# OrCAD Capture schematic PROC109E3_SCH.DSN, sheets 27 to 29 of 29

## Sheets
27 27. BOARD POWER 01: size C; title: BOARD POWER_01
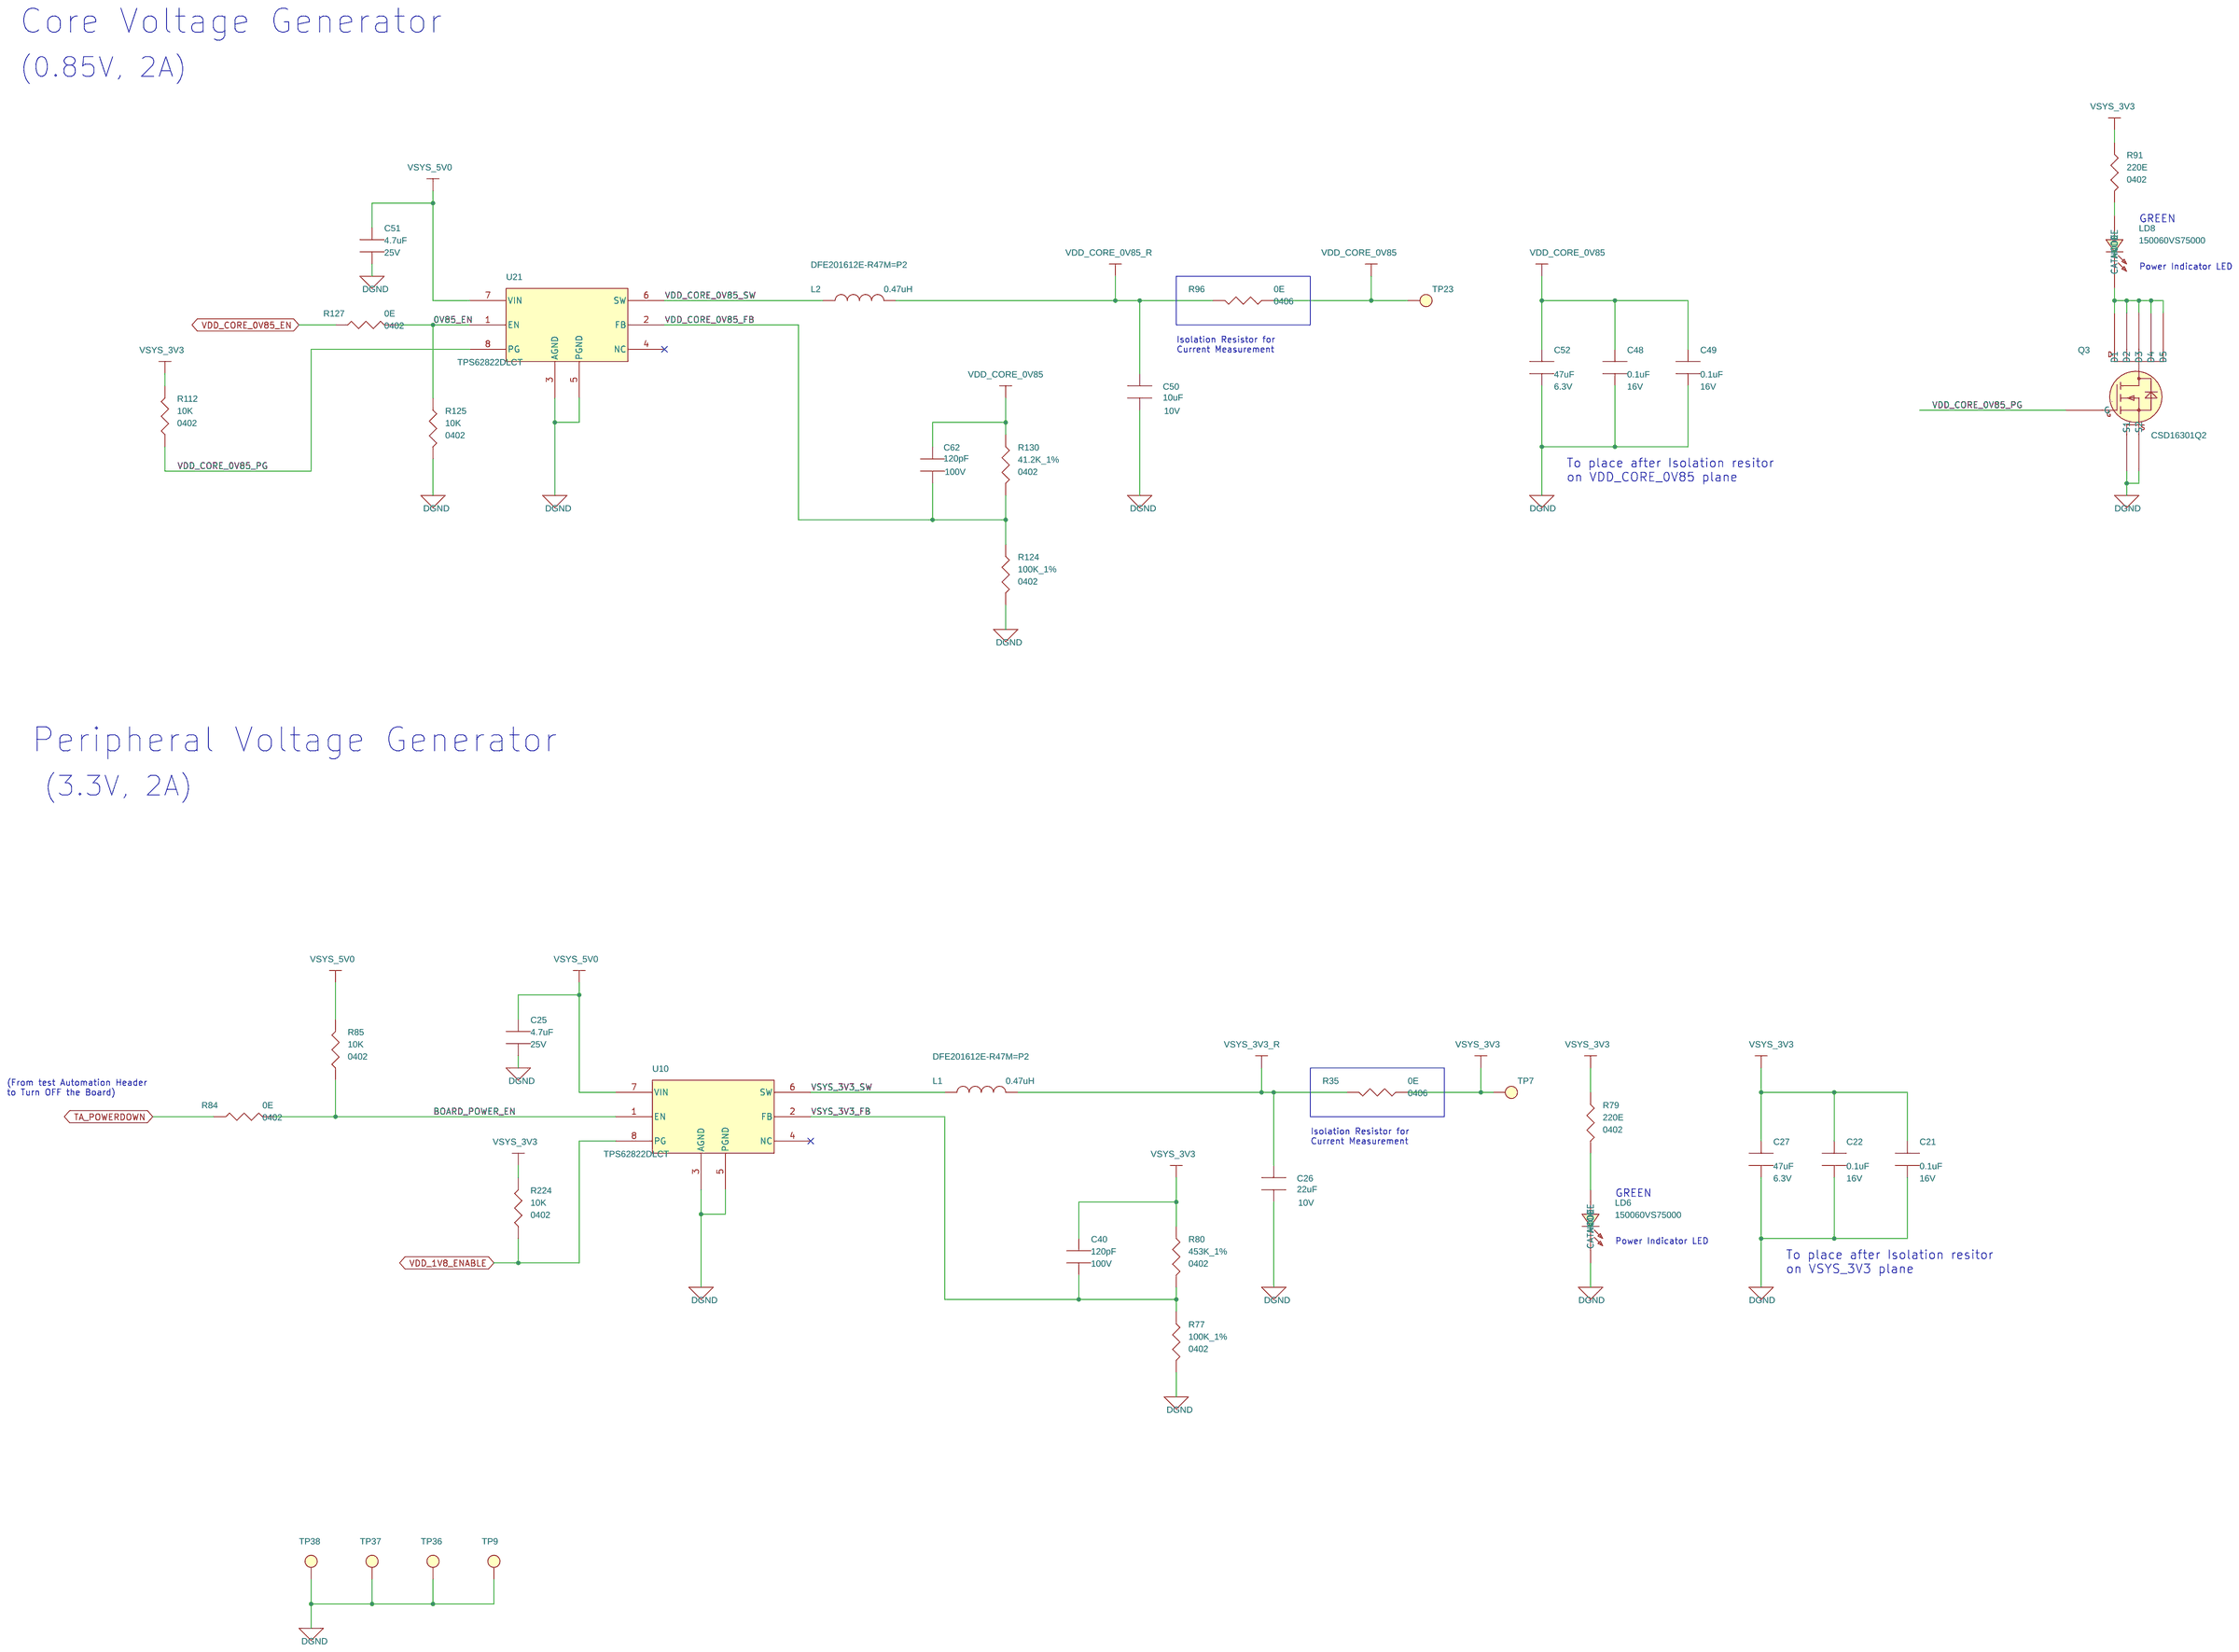
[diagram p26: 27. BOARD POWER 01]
28 28. BOARD POWER 02: size C; title: BOARD POWER_02
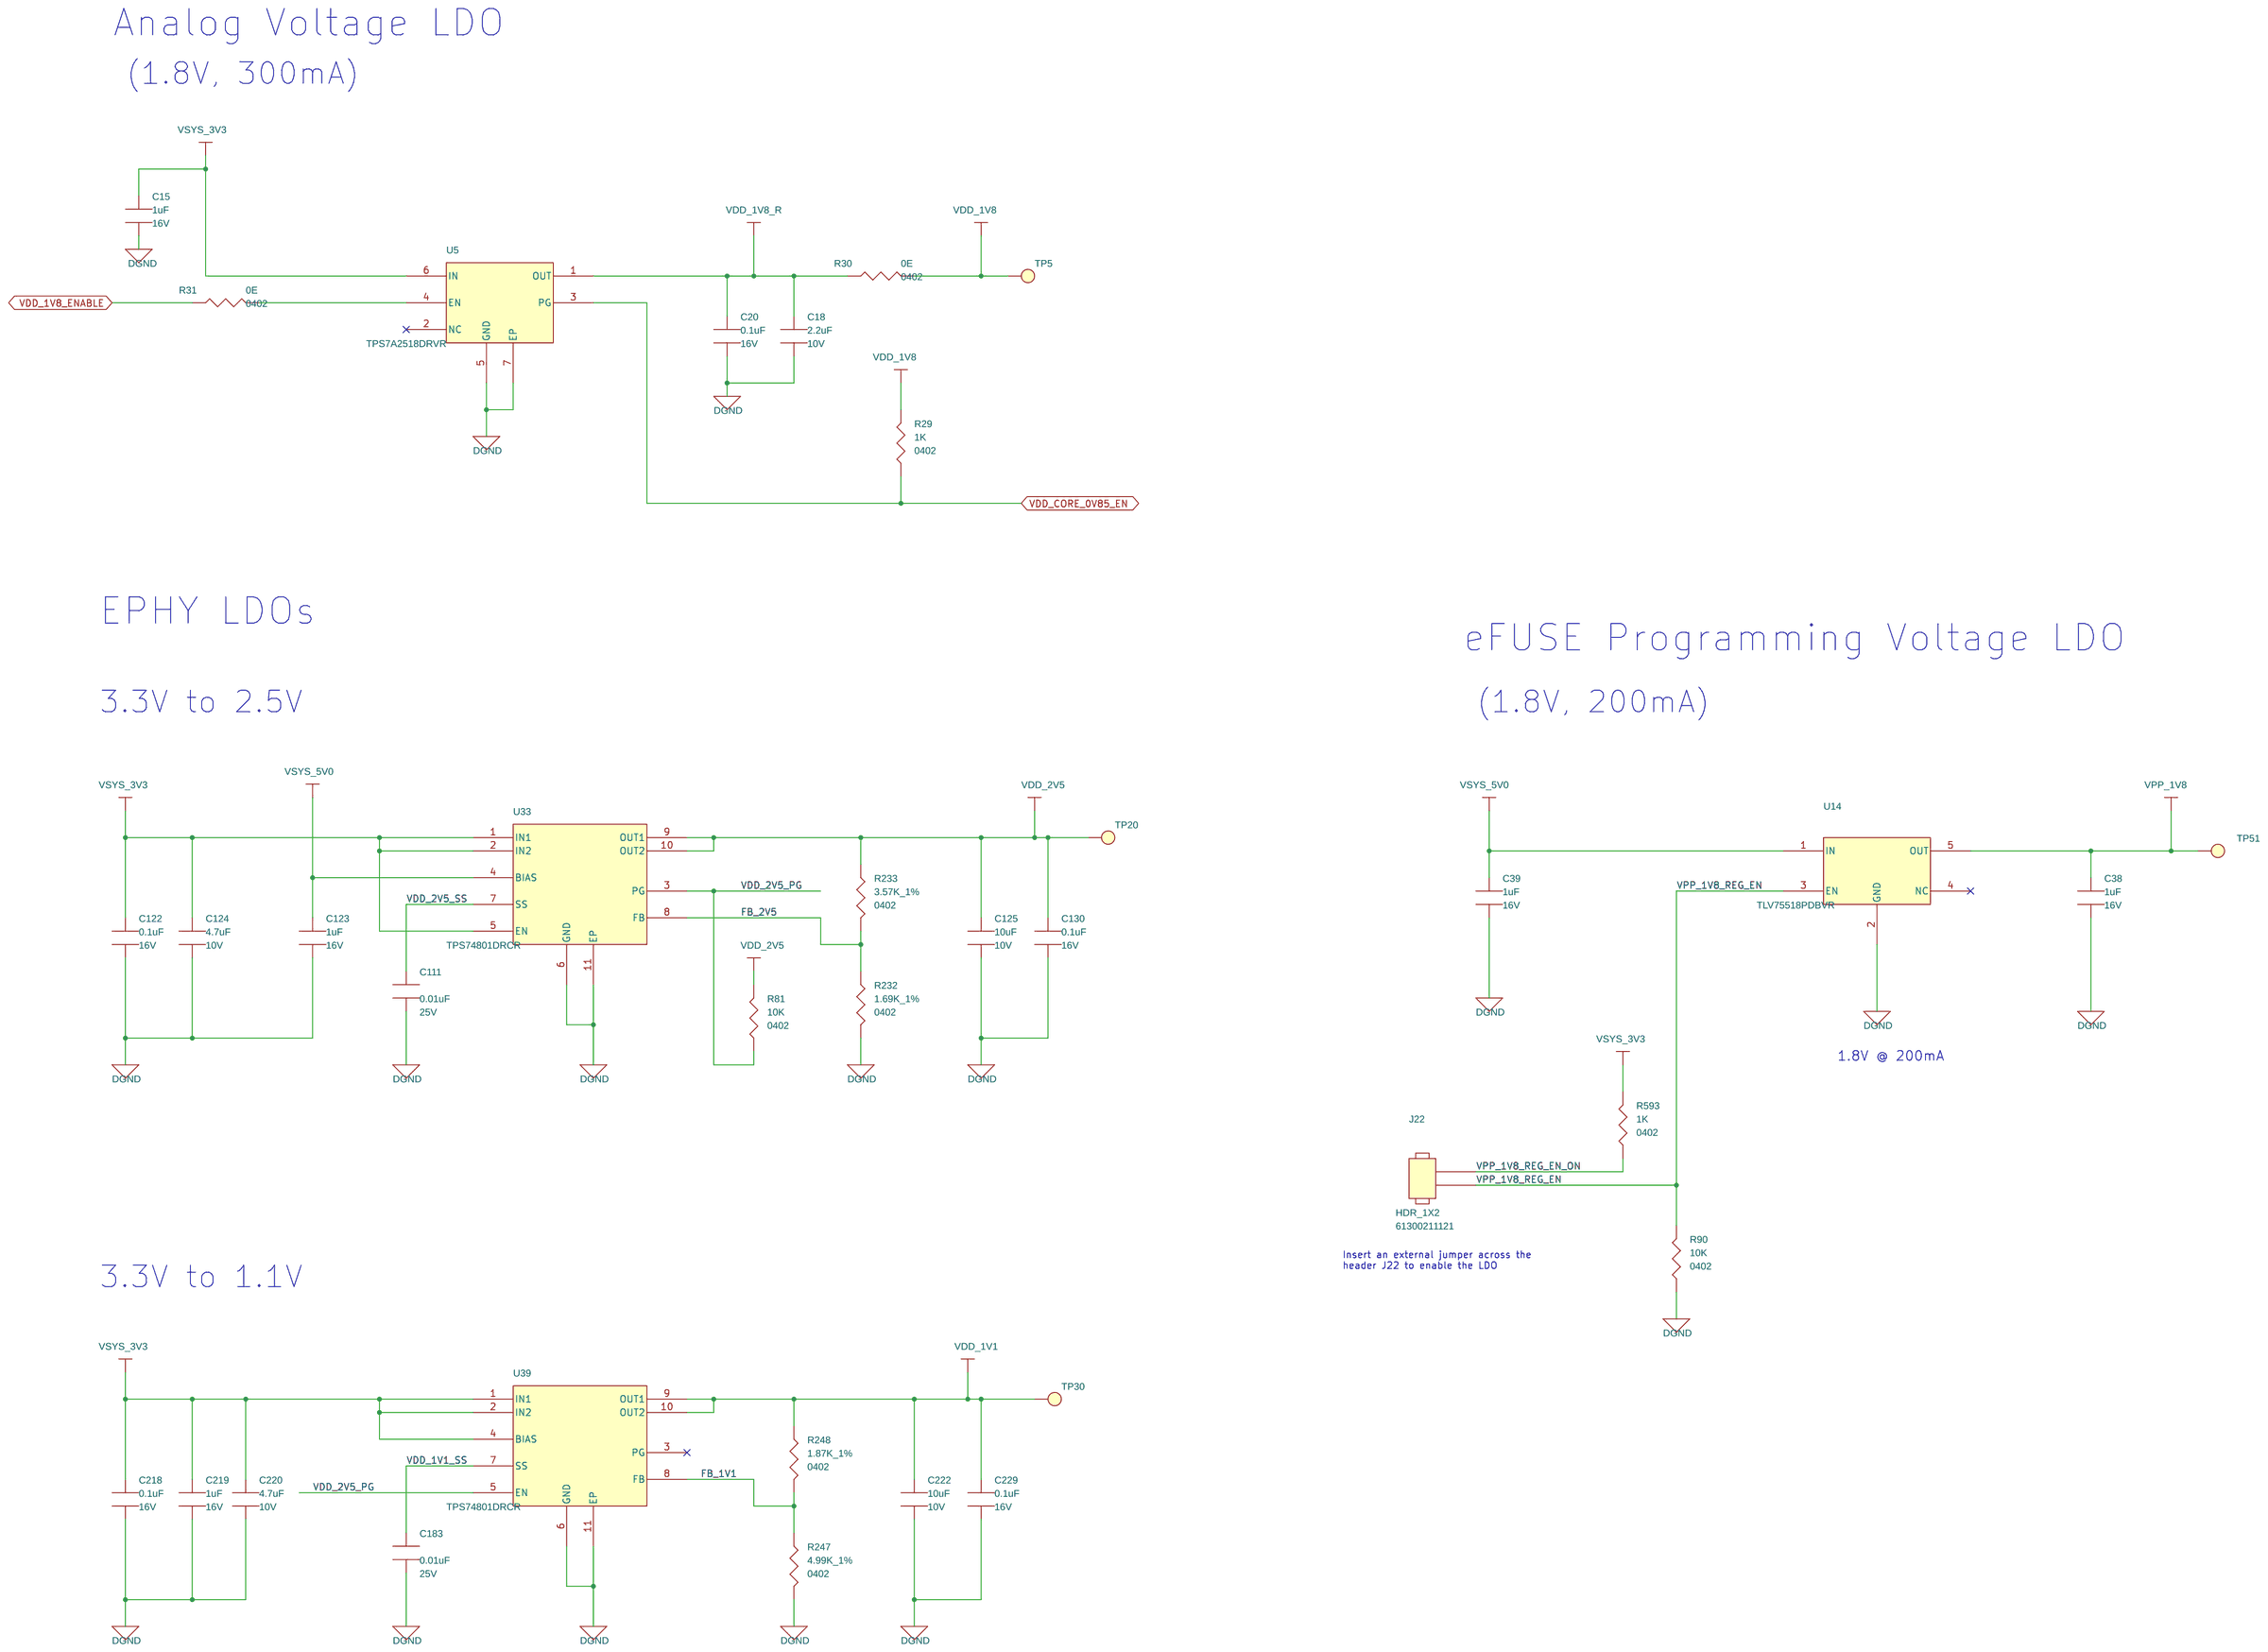
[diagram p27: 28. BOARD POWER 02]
29 29. HARDWARE_SCHEMATICS: title: HARDWARE SCHEMATICS
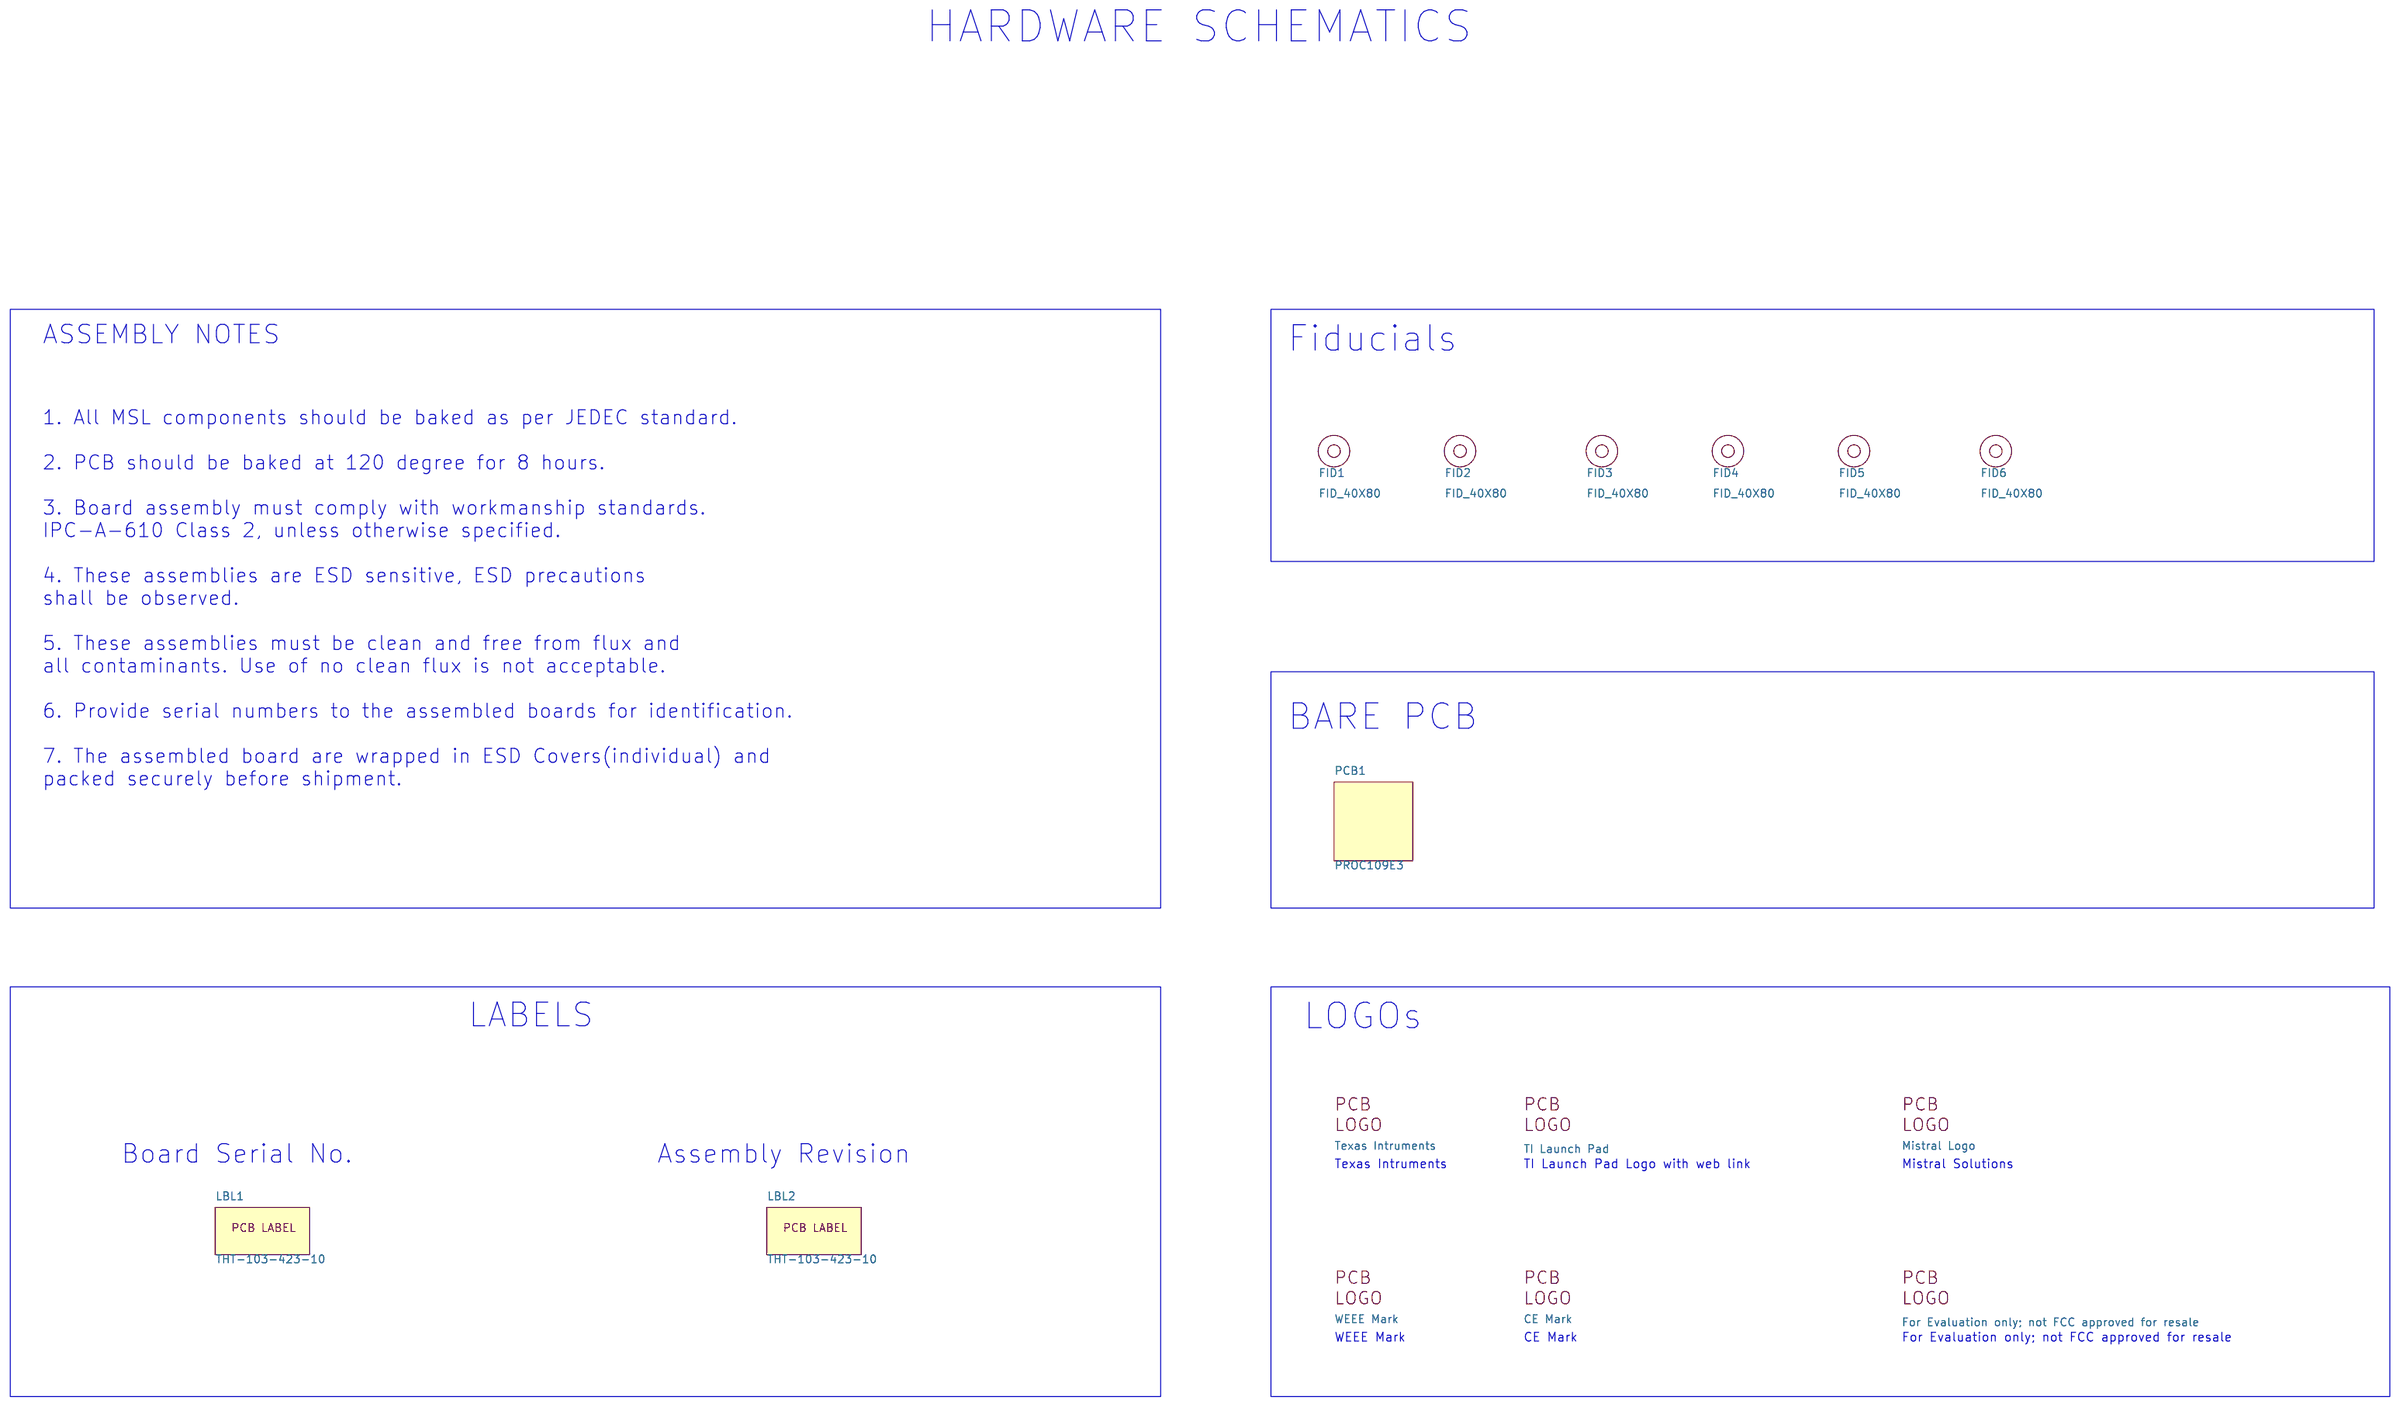
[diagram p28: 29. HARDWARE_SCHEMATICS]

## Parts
sheet 27. BOARD POWER 01
C21  0.1uF  [CAP0201_0-5]
C22  0.1uF  [CAP0201_0-5]
C25  4.7uF  [CAP1206_2]
C26  22uF  [CAP0603_1]
C27  47uF  [CAP0603_1]
C40  120pF  [CAP0402_0-75]
C48  0.1uF  [CAP0201_0-5]
C49  0.1uF  [CAP0201_0-5]
C50  10uF  [CAP0402_0-75]
C51  4.7uF  [CAP1206_2]
C52  47uF  [CAP0603_1]
C62  120pF  [CAP0402_0-75]
L1  0.47uH  [IND0806_1-2]
L2  0.47uH  [IND0806_1-2]
LD6  150060VS75000  [LED_150060SS75000_70X40_SMD_0-8]
LD8  150060VS75000  [LED_150060SS75000_70X40_SMD_0-8]
Q3  CSD16301Q2  [WSON6_CSD13202Q2_80X80_0-8]
R35  0E  [RES0406_0-5]
R77  100K_1%  [RES0402_0-5]
R79  220E  [RES0402_0-5]
R80  453K_1%  [RES0402_0-5]
R84  0E  [RES0402_0-5]
R85  10K  [RES0402_0-5]
R91  220E  [RES0402_0-5]
R96  0E  [RES0406_0-5]
R112  10K  [RES0402_0-5]
R124  100K_1%  [RES0402_0-5]
R125  10K  [RES0402_0-5]
R127  0E  [RES0402_0-5]
R130  41.2K_1%  [RES0402_0-5]
R224  10K  [RES0402_0-5]
TP7  TP40_SMD  [TP40_SMD]
TP9  THRU HOLE  [TP_40X65]
TP23  TP40_SMD  [TP40_SMD]
TP36  THRU HOLE  [TP_40X65]
TP37  THRU HOLE  [TP_40X65]
TP38  THRU HOLE  [TP_40X65]
U10  TPS62822DLCT  [VSONHR8_TPS62823_60X80_1]
U21  TPS62822DLCT  [VSONHR8_TPS62823_60X80_1]
sheet 28. BOARD POWER 02
C15  1uF  [CAP0201_0-5]
C18  2.2uF  [CAP0402_0-75]
C20  0.1uF  [CAP0201_0-5]
C38  1uF  [CAP0201_0-5]
C39  1uF  [CAP0201_0-5]
C111  0.01uF  [CAP0201_0-5]
C122  0.1uF  [CAP0201_0-5]
C123  1uF  [CAP0201_0-5]
C124  4.7uF  [CAP0402_0-75]
C125  10uF  [CAP0402_0-75]
C130  0.1uF  [CAP0201_0-5]
C183  0.01uF  [CAP0201_0-5]
C218  0.1uF  [CAP0201_0-5]
C219  1uF  [CAP0201_0-5]
C220  4.7uF  [CAP0402_0-75]
C222  10uF  [CAP0402_0-75]
C229  0.1uF  [CAP0201_0-5]
J22  HDR_1X2  [HDR_1X2_61300211121_S_T_8-6]
R29  1K  [RES0402_0-5]
R30  0E  [RES0402_0-5]
R31  0E  [RES0402_0-5]
R81  10K  [RES0402_0-5]
R90  10K  [RES0402_0-5]
R232  1.69K_1%  [RES0402_0-5]
R233  3.57K_1%  [RES0402_0-5]
R247  4.99K_1%  [RES0402_0-5]
R248  1.87K_1%  [RES0402_0-5]
R593  1K  [RES0402_0-5]
TP5  TP40_SMD  [TP40_SMD]
TP20  TP40_SMD  [TP40_SMD]
TP30  TP40_SMD  [TP40_SMD]
TP51  TP20_SMD  [TP20_SMD]
U5  TPS7A2518DRVR  [SON6_25-59_85X85_0-8]
U14  TLV75518PDBVR  [SOT23-5_1-5]
U33  TPS74801DRCR  [VSON10_TPS74801-Q1_120X120_1]
U39  TPS74801DRCR  [VSON10_TPS74801-Q1_120X120_1]
sheet 29. HARDWARE_SCHEMATICS
FID1  FID_40X80  [FID_40X80]
FID2  FID_40X80  [FID_40X80]
FID3  FID_40X80  [FID_40X80]
FID4  FID_40X80  [FID_40X80]
FID5  FID_40X80  [FID_40X80]
FID6  FID_40X80  [FID_40X80]
LBL1  THT-103-423-10  [NA]
LBL2  THT-103-423-10  [NA]
LOGO1  Texas Intruments  [TI_Stacked_Overlay_Small]
LOGO2  TI Launch Pad  [FCC_disclaimer]
LOGO3  Mistral Logo  [TI_Stacked_Overlay_Small]
LOGO4  WEEE Mark  [TI_Stacked_Overlay_Small]
LOGO5  CE Mark  [TI_Stacked_Overlay_Small]
LOGO6  For Evaluation only; not FCC approved for resale  [FCC_disclaimer]
PCB1  PROC109E3

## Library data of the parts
C20-C22 C48 C49 C122 C130 C218 C229 = CAP: CAP CERAMIC 0.1uF 16V 10% X5R 0201; Chkd/date: MANIRAJA/230118; Crtd /date: MANIRAJA/230118; Custom_Duty: 15%; Customs_HS_Code: 85322990; Distributor_name: DIGIKEY; Distributor_part_number: 490-14305-1-ND; Footprint Path: Y:\MIS_DATABASE\Library\ALTIUM_TOOL\PCB_FOOTPRINTS\Altium_Footprint_Lib.PcbLib; Height: 0.33MM; Library Path: Y:\MIS_DATABASE\Library\ALTIUM_TOOL\SCHEMATICS_PARTS\MS_DISCRETE_Library.schlib; Mfr_name: MURATA; Mfr_part_number: GRM033R61C104KE14D; Mistral Part No: 120009030072-R; Package: 0201; Part_type: CAPACITORS\CERAMIC; Project: TI_MAXIE_CPB; RoHS: RoHS; Temperature: -55°C+85°C; Tolerance: 10%; Voltage: 16V; Wattage: NA; Weight: 0.33mg; Datasheet: Y:\MIS_DATABASE\DATASHEETS\CAPACITORS\GRM033R61C104KE14.PDF
C25 C51 = CAP: CAP CERAMIC 4.7uF 25V 20% X5R 1206; Chkd/date: MANIRAJA/280121; Crtd /date: ALVY/280121; Custom_Duty: 15%; Customs_HS_Code: 85322990; Distributor_name: DIGIKEY; Distributor_part_number: 732-7644-1-ND; Footprint Path: Y:\MIS_DATABASE\Library\ALTIUM_TOOL\PCB_FOOTPRINTS\Altium_Footprint_Lib.PcbLib; Height: 1.90MM; Library Path: Y:\MIS_DATABASE\Library\ALTIUM_TOOL\SCHEMATICS_PARTS\MS_DISCRETE_Library.schlib; Mfr_name: WURTH ELECTRONICS; Mfr_part_number: 885012108020; Mistral Part No: 120021010031-R; Package: 1206; Part_type: CAPACITORS\CERAMIC; Project: TI_AM243x LP EVM; RoHS: RoHS; Temperature: -55°C+85°C; Tolerance: 20%; Voltage: 25V; Wattage: NA; Weight: 16.2mg; Datasheet: Y:\MIS_DATABASE\DATASHEETS\CAPACITORS\885012108020.PDF
C26 = CAP: CAP CERAMIC 22uF 10V 20% X5R 0603; Chkd/date: MANIRAJA/230118; Crtd /date: MANIRAJA/230118; Custom_Duty: 15%; Customs_HS_Code: 85322990; Distributor_name: DIGIKEY; Distributor_part_number: 490-10476-1-ND; Footprint Path: Y:\MIS_DATABASE\Library\ALTIUM_TOOL\PCB_FOOTPRINTS\Altium_Footprint_Lib.PcbLib; Height: 1.00MM; Library Path: Y:\MIS_DATABASE\Library\ALTIUM_TOOL\SCHEMATICS_PARTS\MS_DISCRETE_Library.schlib; Mfr_name: MURATA; Mfr_part_number: GRM188R61A226ME15D; Mistral Part No: 120014100009-R; Package: 0603; Part_type: CAPACITORS\CERAMIC; Project: TI_MAXIE_CPB; RoHS: RoHS; Temperature: -55°C+85°C; Tolerance: 20%; Voltage: 10V; Wattage: NA; Weight: 6.3mg; Datasheet: Y:\MIS_DATABASE\DATASHEETS\CAPACITORS\GRM188R61A226ME15.PDF
C27 C52 = CAP: CAP CERAMIC 47uF 6.3V 20% X5R 0603; Chkd/date: VASANTHA/211116; Crtd /date: MANIRAJA/211116; Custom_Duty: 15%; Customs_HS_Code: 85322990; Distributor_name: DIGIKEY; Distributor_part_number: 490-13247-1-ND; Footprint Path: Y:\MIS_DATABASE\Library\ALTIUM_TOOL\PCB_FOOTPRINTS\Altium_Footprint_Lib.PcbLib; Height: 1.00MM; Library Path: Y:\MIS_DATABASE\Library\ALTIUM_TOOL\SCHEMATICS_PARTS\MS_DISCRETE_Library.schlib; Mfr_name: MURATA; Mfr_part_number: GRM188R60J476ME15D; Mistral Part No: 120016110001-R; Package: 0603; Part_type: CAPACITORS\CERAMIC; Project: DLRL_3U_ESM_VPX; RoHS: RoHS; Temperature: -55°C+85°C; Tolerance: 20%; Voltage: 6.3V; Wattage: NA; Weight: 6.3mg; Datasheet: Y:\MIS_DATABASE\DATASHEETS\CAPACITORS\MURATA-GXX-SER_NOV17.PDF
C40 C62 = CAP: CAP CERAMIC 120pF 100V 5% C0G(NP0) 0402; Alternate_mfr_part_number_A: GCM1555C1H121JA16D; Chkd/date: MANIRAJA/280121; Crtd /date: ALVY/280121; Custom_Duty: 15%; Customs_HS_Code: 85322990; Distributor_name: MOUSER; Distributor_part_number: 81-GRM1555C2A121JE1D; Footprint Path: Y:\MIS_DATABASE\Library\ALTIUM_TOOL\PCB_FOOTPRINTS\Altium_Footprint_Lib.PcbLib; Height: 0.55MM; Library Path: Y:\MIS_DATABASE\Library\ALTIUM_TOOL\SCHEMATICS_PARTS\MS_DISCRETE_Library.schlib; Mfr_name: MURATA; Mfr_part_number: GRM1555C2A121JE01D; Mistral Part No: 120021010032-R; Package: 0402; Part_type: CAPACITORS\CERAMIC; Project: TI_AM243x LP EVM; RoHS: RoHS; Temperature: -55°C+125°C; Tolerance: 5%; Voltage: 100V; Wattage: NA; Weight: 1.6mg; Datasheet: Y:\MIS_DATABASE\DATASHEETS\CAPACITORS\GRM1555C2A121JE01.PDF
C50 C125 C222 = CAP: CAP CERAMIC 10uF 10V 20% X5R 0402; Chkd/date: MANIRAJA/300520; Crtd /date: ALVY/260520; Custom_Duty: 15%; Customs_HS_Code: 85322990; Distributor_name: DIGIKEY; Distributor_part_number: 490-GRM155R61A106ME11DTR-ND; Footprint Path: Y:\MIS_DATABASE\Library\ALTIUM_TOOL\PCB_FOOTPRINTS\Altium_Footprint_Lib.PcbLib; Height: 0.55MM; Library Path: Y:\MIS_DATABASE\Library\ALTIUM_TOOL\SCHEMATICS_PARTS\MS_DISCRETE_Library.schlib; Mfr_name: MURATA; Mfr_part_number: GRM155R61A106ME11D; Mistral Part No: 120013110019-R; Package: 0402; Part_type: CAPACITORS\CERAMIC; Project: QCS610_NANOSOM; RoHS: RoHS; Temperature: -55°C+85°C; Tolerance: 20%; Voltage: 10V; Wattage: NA; Weight: 3.1mg; Datasheet: Y:\MIS_DATABASE\DATASHEETS\CAPACITORS\MURATA-GXX-SER_NOV17.PDF
L1 L2 = INDUCTOR: IND CHIP 0.47uH 4.5A 20% 0806; Chkd/date: MANIRAJA/121020; Crtd /date: ALVY/121020; Custom_Duty: 24%; Customs_HS_Code: 85437099; Distributor_name: DIGIKEY; Distributor_part_number: DFE201612E-R47M=P2-ND; Footprint Path: Y:\MIS_DATABASE\Library\ALTIUM_TOOL\PCB_FOOTPRINTS\Altium_Footprint_Lib.PcbLib; Height: 1.20MM; Library Path: Y:\MIS_DATABASE\Library\ALTIUM_TOOL\SCHEMATICS_PARTS\MS_DISCRETE_Library.schlib; Mfr_name: MURATA; Mfr_part_number: DFE201612E-R47M=P2; Mistral Part No: 130020100030-R; Package: 0806; Project: AM64X_SKEVM; RoHS: RoHS; Temperature: -40°C+125°C; Tolerance: 20%; Voltage: NA; Wattage: NA; Weight: 18.8mg; Datasheet: Y:\MIS_DATABASE\DATASHEETS\DISCRETES\INDUCTORS\DFE201612E.PDF
LD6 LD8 = DIODE_LED: DIODE LED BRIGHT GREEN SMD; Chkd/date: MANIRAJA/220720; Crtd /date: ALVY/210720; Custom_Duty: 24%; Customs_HS_Code: 85439000; Distributor_name: DIGIKEY; Distributor_part_number: 732-4980-1-ND; Footprint Path: Y:\MIS_DATABASE\Library\ALTIUM_TOOL\PCB_FOOTPRINTS\Altium_Footprint_Lib.PcbLib; Height: 0.80MM; Library Path: Y:\MIS_DATABASE\Library\ALTIUM_TOOL\SCHEMATICS_PARTS\MS_OPTO_Library.schlib; Mfr_name: WURTH ELECTRONICS; Mistral Part No: 130020070019-R; Package: SMD; Part_type: OPTO\LED; Project: AM64x-IO LINK BRD; RoHS: RoHS; Temperature: -40°C+85°C; Tolerance: NA; Voltage: NA; Wattage: NA; Weight: 25mg; Datasheet: Y:\MIS_DATABASE\DATASHEETS\DISCRETES\LEDS\150060VS75000.PDF
Q3 = MOSFET_CSD17313Q2: IC MOSFET N-CHANNEL NEXFET 25V WSON6; Chkd/date: ALVY/071220; Crtd /date: MANIRAJA/071220; Custom_Duty: 15%; Customs_HS_Code: 85423100; Distributor_name: DIGIKEY; Distributor_part_number: 296-25260-1-ND; Footprint Path: Y:\MIS_DATABASE\Library\ALTIUM_TOOL\PCB_FOOTPRINTS\Altium_Footprint_Lib.PcbLib; Height: 0.80MM; Library Path: Y:\MIS_DATABASE\Library\ALTIUM_TOOL\SCHEMATICS_PARTS\MS_MOSFET_Library.schlib; Mfr_name: TEXAS INSTRUMENTS; Mistral Part No: 142020120008-R; Package: WSON6; Part_type: ICS\POWER\MOSFET; Project: TI_AM243x LP EVM; RoHS: RoHS; Temperature: -55°C+150°C; Tolerance: NA; Voltage: NA; Wattage: NA; Weight: 8.7mg; Datasheet: Y:\MIS_DATABASE\DATASHEETS\ICS\POWER\CSD16301Q2.PDF
R35 R96 = RESISTOR: RES 0E 1/4W JUMPER 0406; Chkd/date: MANIRAJA/250620; Crtd /date: ALVY/240620; Custom_Duty: 15%; Customs_HS_Code: 85332119; Distributor_name: DIGIKEY; Distributor_part_number: 749-1060-1-ND; Footprint Path: Y:\MIS_DATABASE\Library\ALTIUM_TOOL\PCB_FOOTPRINTS\Altium_Footprint_Lib.PcbLib; Height: 0.45MM; Library Path: Y:\MIS_DATABASE\Library\ALTIUM_TOOL\SCHEMATICS_PARTS\MS_DISCRETE_Library.schlib; Mfr_name: VISHAY; Mfr_part_number: RCA04060000Z0EALS; Mistral Part No: 110020060042-R; Package: 0406; Part_type: RESISTORS\FIXED; Project: ISSI TDA4VM; RoHS: RoHS; Temperature: -55°C+155°C; Tolerance: NA; Voltage: NA; Wattage: NA; Weight: 2mg; Datasheet: Y:\MIS_DATABASE\DATASHEETS\RESISTORS\RCA-LS.PDF
R77 R124 = RESISTOR: RES 100K 1/16W 1% 0402; Chkd/date: MANIRAJA/110917; Crtd /date: MANIRAJA/110917; Custom_Duty: 15%; Customs_HS_Code: 85332119; Distributor_name: DIGIKEY; Distributor_part_number: 311-100KLRCT-ND; Footprint Path: Y:\MIS_DATABASE\Library\ALTIUM_TOOL\PCB_FOOTPRINTS\Altium_Footprint_Lib.PcbLib; Height: 0.40MM; Library Path: Y:\MIS_DATABASE\Library\ALTIUM_TOOL\SCHEMATICS_PARTS\MS_DISCRETE_Library.schlib; Mfr_name: YAGEO AMERICA; Mfr_part_number: RC0402FR-07100KL; Mistral Part No: 110014060043-R; Package: 0402; Part_type: RESISTORS\FIXED; Project: CRADE RF CARD; RoHS: RoHS; Temperature: -55°C+155°C; Tolerance: 1%; Voltage: NA; Wattage: 1/16W; Weight: 0.65mg; Datasheet: Y:\MIS_DATABASE\DATASHEETS\RESISTORS\RCXXXXL-SER_MAR18.PDF
R79 R91 = RESISTOR: RES 220E 1/16W 5% 0402; Chkd/date: ALVY/091220; Crtd /date: MANIRAJA/091220; Custom_Duty: 15%; Customs_HS_Code: 85332119; Distributor_name: DIGIKEY; Distributor_part_number: 311-220JRCT-ND; Footprint Path: Y:\MIS_DATABASE\Library\ALTIUM_TOOL\PCB_FOOTPRINTS\Altium_Footprint_Lib.PcbLib; Height: 0.40MM; Library Path: Y:\MIS_DATABASE\Library\ALTIUM_TOOL\SCHEMATICS_PARTS\MS_DISCRETE_Library.schlib; Mfr_name: YAGEO AMERICA; Mfr_part_number: RC0402JR-07220RL; Mistral Part No: 110020120013-R; Package: 0402; Part_type: RESISTORS\FIXED; Project: TI_AM243x LP EVM; RoHS: RoHS; Temperature: -55°C+155°C; Tolerance: 5%; Voltage: NA; Wattage: 1/16W; Weight: 0.65mg; Datasheet: Y:\MIS_DATABASE\DATASHEETS\RESISTORS\RCXXXXL-SER_MAR18.PDF
R80 = RESISTOR: RES 453K 1/16W 1% 0402; Chkd/date: MANIRAJA/150519; Crtd /date: MANIRAJA/150519; Custom_Duty: 15%; Customs_HS_Code: 85332119; Distributor_name: DIGIKEY; Distributor_part_number: YAG3164CT-ND; Footprint Path: Y:\MIS_DATABASE\Library\ALTIUM_TOOL\PCB_FOOTPRINTS\Altium_Footprint_Lib.PcbLib; Height: 0.40MM; Library Path: Y:\MIS_DATABASE\Library\ALTIUM_TOOL\SCHEMATICS_PARTS\MS_DISCRETE_Library.schlib; Mfr_name: YAGEO AMERICA; Mfr_part_number: RC0402FR-07453KL; Mistral Part No: 110019050018-R; Package: 0402; Part_type: RESISTORS\FIXED; Project: AM654x SOM_TEST_JIG; RoHS: RoHS; Temperature: -55°C+155°C; Tolerance: 1%; Voltage: NA; Wattage: 1/16W; Weight: 0.65mg; Datasheet: Y:\MIS_DATABASE\DATASHEETS\RESISTORS\RCXXXXL-SER_MAR18.PDF
R30 R31 R84 R127 = RESISTOR: RES 0E 1/16W 5% 0402; Chkd/date: VASANTHA/291216; Crtd /date: CHAITHANYA/300911; Custom_Duty: 15%; Customs_HS_Code: 85332119; Distributor_name: DIGIKEY; Distributor_part_number: 311-0.0JRCT-ND; Footprint Path: Y:\MIS_DATABASE\Library\ALTIUM_TOOL\PCB_FOOTPRINTS\Altium_Footprint_Lib.PcbLib; Height: 0.40MM; Library Path: Y:\MIS_DATABASE\Library\ALTIUM_TOOL\SCHEMATICS_PARTS\MS_DISCRETE_Library.schlib; Mfr_name: YAGEO AMERICA; Mfr_part_number: RC0402JR-070RL; Mistral Part No: 110011090036-R; Package: 0402; Part_type: RESISTORS\FIXED; Project: VP-4000-PROCESSOR; RoHS: RoHS; Temperature: -55°C+155°C; Tolerance: 5%; Voltage: NA; Wattage: 1/16W; Weight: 0.65mg; Datasheet: Y:\MIS_DATABASE\DATASHEETS\RESISTORS\RCXXXXL-SER_MAR18.PDF
R81 R85 R90 R112 R125 R224 = RESISTOR: RES 10K 1/16W 5% 0402; Chkd/date: VASANTHA/061216; Crtd /date: MAZHAR/230805; Custom_Duty: 15%; Customs_HS_Code: 85332119; Distributor_name: DIGIKEY; Distributor_part_number: 311-10KJRCT-ND; Footprint Path: Y:\MIS_DATABASE\Library\ALTIUM_TOOL\PCB_FOOTPRINTS\Altium_Footprint_Lib.PcbLib; Height: 0.40MM; Library Path: Y:\MIS_DATABASE\Library\ALTIUM_TOOL\SCHEMATICS_PARTS\MS_DISCRETE_Library.schlib; Mfr_name: YAGEO AMERICA; Mfr_part_number: RC0402JR-0710KL; Mistral Part No: 110011060021-R; Package: 0402; Part_type: RESISTORS\FIXED; Project: HSE; RoHS: RoHS; Temperature: -55°C+155°C; Tolerance: 5%; Voltage: NA; Wattage: 1/16W; Weight: 0.65mg; Datasheet: Y:\MIS_DATABASE\DATASHEETS\RESISTORS\RCXXXXL-SER_MAR18.PDF
R130 = RESISTOR: RES 41.2K 1/16W 1% 0402; Chkd/date: ALVY/091220; Crtd /date: MANIRAJA/091220; Custom_Duty: 15%; Customs_HS_Code: 85332119; Distributor_name: DIGIKEY; Distributor_part_number: YAG3155CT-ND; Footprint Path: Y:\MIS_DATABASE\Library\ALTIUM_TOOL\PCB_FOOTPRINTS\Altium_Footprint_Lib.PcbLib; Height: 0.40MM; Library Path: Y:\MIS_DATABASE\Library\ALTIUM_TOOL\SCHEMATICS_PARTS\MS_DISCRETE_Library.schlib; Mfr_name: YAGEO AMERICA; Mfr_part_number: RC0402FR-0741K2L; Mistral Part No: 110020050005-R; Package: 0402; Part_type: RESISTORS\FIXED; Project: TI_AM243x LP EVM; RoHS: RoHS; Temperature: -55°C+155°C; Tolerance: 1%; Voltage: NA; Wattage: 1/16W; Weight: 0.65mg; Datasheet: Y:\MIS_DATABASE\DATASHEETS\RESISTORS\RCXXXXL-SER_MAR18.PDF
TP5 TP7 TP20 TP23 TP30 = TESTPOINT: TESTPOINT CIR 40 SMD; Chkd/date: MAZHAR/190505; Crtd /date: MAZHAR/190505; Distributor_name: NA; Distributor_part_number: NA; Footprint Path: Y:\MIS_DATABASE\Library\ALTIUM_TOOL\PCB_FOOTPRINTS\Altium_Footprint_Lib.PcbLib; Height: NA; Library Path: Y:\MIS_DATABASE\Library\ALTIUM_TOOL\SCHEMATICS_PARTS\MS_DISCRETE_Library.schlib; MECHANICAL 3D STEP FILE: NA; Mfr_name: LOCAL; Mistral Part No: 130009030933; Package: SMD; Project: RAINIER-3; RoHS: NA; Temperature: NA; Tolerance: NA; Voltage: NA; Wattage: NA; Weight: NA; Datasheet: NA
TP9 TP36-TP38 = TESTPOINT: TESTPOINT 1.0MM DRILL PTH; Chkd/date: MAZHAR/271211; Crtd /date: SHREESHAIL/041005; Distributor_name: NA; Distributor_part_number: NA; Height: NA; Mfr_name: LOCAL; Mistral Part No: 130009030938; Package: THRU-HOLE; Project: HSE; Datasheet: NA
U10 U21 = TPS62823_VSONHR8: IC 2A ADJ STEP-DOWN CONVERTER WITH 1% ACCURACY VSON-HR8; Chkd/date: MANIRAJA/121120; Crtd /date: ALVY/111120; Custom_Duty: 15%; Customs_HS_Code: 85423100; Distributor_name: DIGIKEY; Distributor_part_number: 296-49512-1-ND; Footprint Path: Y:\MIS_DATABASE\Library\ALTIUM_TOOL\PCB_FOOTPRINTS\Altium_Footprint_Lib.PcbLib; Height: 1.00MM; Library Path: Y:\MIS_DATABASE\Library\ALTIUM_TOOL\SCHEMATICS_PARTS\MS_MISCPOWER_Library.schlib; Mfr_name: TEXAS INSTRUMENTS; Mistral Part No: 142020110014-R; Package: VSON-HR8; Part_type: ICS\POWER\DC-DC CONVERTER; Project: TI_AM243x LP EVM; RoHS: RoHS; Temperature: -40°C+125°C; Tolerance: NA; Voltage: NA; Wattage: NA; Weight: 6.2mg; Datasheet: Y:\MIS_DATABASE\DATASHEETS\ICS\POWER\TPS62821-2-3.PDF
C15 C38 C39 C123 C219 = CAP: CAP CERAMIC 1uF 16V 20% X5R 0201; Chkd/date: MANIRAJA/300520; Crtd /date: ALVY/260520; Custom_Duty: 15%; Customs_HS_Code: 85322990; Distributor_name: DIGIKEY; Distributor_part_number: 490-18654-1-ND; Footprint Path: Y:\MIS_DATABASE\Library\ALTIUM_TOOL\PCB_FOOTPRINTS\Altium_Footprint_Lib.PcbLib; Height: 0.39MM; Library Path: Y:\MIS_DATABASE\Library\ALTIUM_TOOL\SCHEMATICS_PARTS\MS_DISCRETE_Library.schlib; Mfr_name: MURATA; Mfr_part_number: GRM033R61C105ME15D; Mistral Part No: 120018090038-R; Package: 0201; Part_type: CAPACITORS\CERAMIC; Project: QCS610_NANOSOM; RoHS: RoHS; Temperature: -55°C+85°C; Tolerance: 20%; Voltage: 16V; Wattage: NA; Weight: 0.33mg; Datasheet: Y:\MIS_DATABASE\DATASHEETS\CAPACITORS\GRM033R61C105ME15.PDF
C18 = CAP: CAP CERAMIC 2.2uF 10V 20% X5R 0402; Chkd/date: MANIRAJA/170820; Crtd /date: ALVY/170820; Custom_Duty: 15%; Customs_HS_Code: 85322990; Distributor_name: DIGIKEY; Distributor_part_number: 732-7490-1-ND; Footprint Path: Y:\MIS_DATABASE\Library\ALTIUM_TOOL\PCB_FOOTPRINTS\Altium_Footprint_Lib.PcbLib; Height: 0.55MM; Library Path: Y:\MIS_DATABASE\Library\ALTIUM_TOOL\SCHEMATICS_PARTS\MS_DISCRETE_Library.schlib; Mfr_name: WURTH ELECTRONICS; Mfr_part_number: 885012105013; Mistral Part No: 120019040036-R; Package: 0402; Part_type: CAPACITORS\CERAMIC; Project: AM64x_EVM_BRD; RoHS: RoHS; Temperature: -55°C+85°C; Tolerance: 20%; Voltage: 10V; Wattage: NA; Weight: 0.65mg; Datasheet: Y:\MIS_DATABASE\DATASHEETS\CAPACITORS\885012105013.PDF
C111 C183 = CAP: CAP CERAMIC 0.01uF 25V 10% X7R 0201; Chkd/date: MANIRAJA/080519; Crtd /date: ALVY/080519; Custom_Duty: 15%; Customs_HS_Code: 85322990; Distributor_name: DIGIKEY; Distributor_part_number: 490-14454-1-ND; Footprint Path: Y:\MIS_DATABASE\Library\ALTIUM_TOOL\PCB_FOOTPRINTS\Altium_Footprint_Lib.PcbLib; Height: 0.33MM; Library Path: Y:\MIS_DATABASE\Library\ALTIUM_TOOL\SCHEMATICS_PARTS\MS_DISCRETE_Library.schlib; Mfr_name: MURATA; Mfr_part_number: GRM033R71E103KE14D; Mistral Part No: 120019050002-R; Package: 0201; Part_type: CAPACITORS\CERAMIC; Project: BRUKER_SD820_COMMONDO; RoHS: RoHS; Temperature: -55°C+125°C; Tolerance: 10%; Voltage: 25V; Wattage: NA; Weight: 0.33mg; Datasheet: Y:\MIS_DATABASE\DATASHEETS\CAPACITORS\GRM033R71E103KE14.PDF
C124 C220 = CAP: CAP CERAMIC 4.7uF 10V 20% X5R 0402; Chkd/date: MANIRAJA/110718; Crtd /date: ALVY/110718; Custom_Duty: 15%; Customs_HS_Code: 85322990; Distributor_name: DIGIKEY; Distributor_part_number: 490-14306-1-ND; Footprint Path: Y:\MIS_DATABASE\Library\ALTIUM_TOOL\PCB_FOOTPRINTS\Altium_Footprint_Lib.PcbLib; Height: 0.65MM; Library Path: Y:\MIS_DATABASE\Library\ALTIUM_TOOL\SCHEMATICS_PARTS\MS_DISCRETE_Library.schlib; Mfr_name: MURATA; Mfr_part_number: GRM155R61A475MEAAD; Mistral Part No: 120012060002-R; Package: 0402; Part_type: CAPACITORS\CERAMIC; Project: TI_J7SVB_PCIE_ADD-ON-CARD; RoHS: RoHS; Temperature: -55°C+85°C; Tolerance: 20%; Voltage: 10V; Wattage: NA; Weight: 14mg; Datasheet: Y:\MIS_DATABASE\DATASHEETS\CAPACITORS\GRM155R61A475MEAAD.PDF
J22 = HEADER_2X1: CON HDR 1X2 2.54MM PITCH ST TH; Chkd/date: MANIRAJA/031018; Crtd /date: ALVY/031018; Custom_Duty: 24%; Customs_HS_Code: 85369090; Distributor_name: DIGIKEY; Distributor_part_number: 732-5315-ND; Footprint Path: Y:\MIS_DATABASE\Library\ALTIUM_TOOL\PCB_FOOTPRINTS\Altium_Footprint_Lib.PcbLib; Height: 8.54MM; Library Path: Y:\MIS_DATABASE\Library\ALTIUM_TOOL\SCHEMATICS_PARTS\MS_CONNECTOR_Library.schlib; Mfr_name: WURTH ELECTRONICS; Mfr_part_number: 61300211121; Mistral Part No: 150018100003-R; Package: THRU-HOLE; Part_type: CONNECTOR\HEADERS; Project: ALPINE_EVM; RoHS: RoHS; Temperature: -40°C+105°C; Tolerance: NA; Voltage: NA; Wattage: NA; Weight: 120mg; Datasheet: Y:\MIS_DATABASE\DATASHEETS\CONNECTORS\6130XXX.PDF
R29 R593 = RESISTOR: RES 1K 1/16W 5% 0402; Chkd/date: VASANTHA/120516; Crtd /date: VASANTHA/120516; Custom_Duty: 15%; Customs_HS_Code: 85332119; Distributor_name: DIGIKEY; Distributor_part_number: 311-1.0KJRCT-ND; Footprint Path: Y:\MIS_DATABASE\Library\ALTIUM_TOOL\PCB_FOOTPRINTS\Altium_Footprint_Lib.PcbLib; Height: 0.40MM; Library Path: Y:\MIS_DATABASE\Library\ALTIUM_TOOL\SCHEMATICS_PARTS\MS_DISCRETE_Library.schlib; Mfr_name: YAGEO AMERICA; Mfr_part_number: RC0402JR-071KL; Mistral Part No: 110010070006-R; Package: 0402; Part_type: RESISTORS\FIXED; Project: TMDXCSK368; RoHS: RoHS; Temperature: -55°C+155°C; Tolerance: 5%; Voltage: NA; Wattage: 1/16W; Weight: 0.65mg; Datasheet: Y:\MIS_DATABASE\DATASHEETS\RESISTORS\RCXXXXL-SER_MAR18.PDF
R232 = RESISTOR: RES 1.69K 1/16W 1% 0402; Chkd/date: ALVY/091220; Crtd /date: MANIRAJA/091220; Custom_Duty: 15%; Customs_HS_Code: 85332119; Distributor_name: DIGIKEY; Distributor_part_number: YAG3044CT-ND; Footprint Path: Y:\MIS_DATABASE\Library\ALTIUM_TOOL\PCB_FOOTPRINTS\Altium_Footprint_Lib.PcbLib; Height: 0.40MM; Library Path: Y:\MIS_DATABASE\Library\ALTIUM_TOOL\SCHEMATICS_PARTS\MS_DISCRETE_Library.schlib; Mfr_name: YAGEO AMERICA; Mfr_part_number: RC0402FR-071K69L; Mistral Part No: 110018100013-R; Package: 0402; Part_type: RESISTORS\FIXED; Project: TI_AM243x LP EVM; RoHS: RoHS; Temperature: -55°C+155°C; Tolerance: 1%; Voltage: NA; Wattage: 1/16W; Weight: 0.65mg; Datasheet: Y:\MIS_DATABASE\DATASHEETS\RESISTORS\RCXXXXL-SER_MAR18.PDF
R233 = RESISTOR: RES 3.57K 1/16W 1% 0402; Chkd/date: ALVY/091220; Crtd /date: MANIRAJA/091220; Custom_Duty: 15%; Customs_HS_Code: 85332119; Distributor_name: DIGIKEY; Distributor_part_number: YAG3150CT-ND; Footprint Path: Y:\MIS_DATABASE\Library\ALTIUM_TOOL\PCB_FOOTPRINTS\Altium_Footprint_Lib.PcbLib; Height: 0.40MM; Library Path: Y:\MIS_DATABASE\Library\ALTIUM_TOOL\SCHEMATICS_PARTS\MS_DISCRETE_Library.schlib; Mfr_name: YAGEO AMERICA; Mfr_part_number: RC0402FR-073K57L; Mistral Part No: 110009070012-R; Package: 0402; Part_type: RESISTORS\FIXED; Project: TI_AM243x LP EVM; RoHS: RoHS; Temperature: -55°C+155°C; Tolerance: 1%; Voltage: NA; Wattage: 1/16W; Weight: 0.65mg; Datasheet: Y:\MIS_DATABASE\DATASHEETS\RESISTORS\RCXXXXL-SER_MAR18.PDF
R247 = RESISTOR: RES 4.99K 1/16W 1% 0402; Chkd/date: MANIRAJA/181120; Crtd /date: ALVY/171120; Custom_Duty: 15%; Customs_HS_Code: 85332119; Distributor_name: DIGIKEY; Distributor_part_number: 311-4.99KLRCT-ND; Footprint Path: Y:\MIS_DATABASE\Library\ALTIUM_TOOL\PCB_FOOTPRINTS\Altium_Footprint_Lib.PcbLib; Height: 0.40MM; Library Path: Y:\MIS_DATABASE\Library\ALTIUM_TOOL\SCHEMATICS_PARTS\MS_DISCRETE_Library.schlib; Mfr_name: YAGEO AMERICA; Mfr_part_number: RC0402FR-074K99L; Mistral Part No: 110014070062-R; Package: 0402; Part_type: RESISTORS\FIXED; Project: SAMSUNG_STREAM_RF; RoHS: RoHS; Temperature: -55°C+155°C; Tolerance: 1%; Voltage: NA; Wattage: 1/16W; Weight: 9mg; Datasheet: Y:\MIS_DATABASE\DATASHEETS\RESISTORS\RCXXXXL-SER_MAR18.PDF
R248 = RESISTOR: RES 1.87K 1/16W 1% 0402; Chkd/date: ALVY/091220; Crtd /date: MANIRAJA/091220; Custom_Duty: 15%; Customs_HS_Code: 85332119; Distributor_name: DIGIKEY; Distributor_part_number: YAG3048CT-ND; Footprint Path: Y:\MIS_DATABASE\Library\ALTIUM_TOOL\PCB_FOOTPRINTS\Altium_Footprint_Lib.PcbLib; Height: 0.40MM; Library Path: Y:\MIS_DATABASE\Library\ALTIUM_TOOL\SCHEMATICS_PARTS\MS_DISCRETE_Library.schlib; Mfr_name: YAGEO AMERICA; Mfr_part_number: RC0402FR-071K87L; Mistral Part No: 110020120012-R; Package: 0402; Part_type: RESISTORS\FIXED; Project: TI_AM243x LP EVM; RoHS: RoHS; Temperature: -55°C+155°C; Tolerance: 1%; Voltage: NA; Wattage: 1/16W; Weight: 0.65mg; Datasheet: Y:\MIS_DATABASE\DATASHEETS\RESISTORS\RCXXXXL-SER_MAR18.PDF
TP51 = TESTPOINT: TESTPOINT CIR 20 SMD; Chkd/date: SHREESHAIL/171006; Crtd /date: MAZHAR/171006; Custom_Duty: NA; Customs_HS_Code: NA; Distributor_name: NA; Distributor_part_number: NA; Footprint Path: Y:\MIS_DATABASE\Library\ALTIUM_TOOL\PCB_FOOTPRINTS\Altium_Footprint_Lib.PcbLib; Height: NA; Library Path: Y:\MIS_DATABASE\Library\ALTIUM_TOOL\SCHEMATICS_PARTS\MS_DISCRETE_Library.schlib; MECHANICAL 3D STEP FILE: NA; Mfr_name: LOCAL; Mistral Part No: NA; Package: SMD; Project: BT MODULE_CSRBC04; RoHS: NA; Temperature: NA; Tolerance: NA; Voltage: NA; Wattage: NA; Weight: NA; Datasheet: NA
U5 = TPS7A2518_WSON6: IC 1.8V 300mA ULTRA-LOW IQ LOW-DROPOUT LINEAR VOLTAGE REGULATOR WITH POWER-GOOD WSON6; Chkd/date: MANIRAJA/151220; Crtd /date: ALVY/151220; Custom_Duty: 15%; Customs_HS_Code: 85423100; Distributor_name: DIGIKEY; Distributor_part_number: 296-TPS7A2518DRVRCT-ND; Footprint Path: Y:\MIS_DATABASE\Library\ALTIUM_TOOL\PCB_FOOTPRINTS\Altium_Footprint_Lib.PcbLib; Height: 0.80MM; Library Path: Y:\MIS_DATABASE\Library\ALTIUM_TOOL\SCHEMATICS_PARTS\MS_MISCPOWER_Library.schlib; Mfr_name: TEXAS INSTRUMENTS; Mistral Part No: 142020120024-R; Package: WSON6; Part_type: ICS\POWER\VOLTAGE REGULATOR; Project: TI_AM243x LP EVM; RoHS: RoHS; Temperature: -40°C+125°C; Tolerance: NA; Voltage: NA; Wattage: NA; Weight: 10mg; Datasheet: Y:\MIS_DATABASE\DATASHEETS\ICS\POWER\TPS7A2518.PDF
U14 = TLV71318PDBVT_SOT23-5: IC 1.8V 500mA LOW IQ LDO REGULATOR SOT23-5; Chkd/date: MANIRAJA/120121; Crtd /date: MANIRAJA/120121; Custom_Duty: 15%; Customs_HS_Code: 85423100; Distributor_name: DIGIKEY; Distributor_part_number: 296-50410-1-ND; Footprint Path: Y:\MIS_DATABASE\Library\ALTIUM_TOOL\PCB_FOOTPRINTS\Altium_Footprint_Lib.PcbLib; Height: 1.45MM; Library Path: Y:\MIS_DATABASE\Library\ALTIUM_TOOL\SCHEMATICS_PARTS\MS_MISCPOWER_Library.schlib; Mfr_name: TEXAS INSTRUMENTS; Mistral Part No: 142021010009-R; Package: SOT23-5; Part_type: ICS\POWER\VOLTAGE REGULATOR; Project: TI_AM243x LP EVM; RoHS: RoHS; Temperature: -40°C+125°C; Tolerance: NA; Voltage: NA; Wattage: NA; Weight: 32.2mg; Datasheet: Y:\MIS_DATABASE\DATASHEETS\ICS\POWER\TLV755P.PDF
U33 U39 = TPS74801DRCR_SON10: IC 1.5A ADJUSTABLE LDO VOLTAGE REGULATOR WITH PROG SOFT-START VSON10; Chkd/date: MANIRAJA/190218; Crtd /date: USMAN/191208; Custom_Duty: 15%; Customs_HS_Code: 85423100; Distributor_name: DIGIKEY; Distributor_part_number: 296-21563-1-ND; Footprint Path: Y:\MIS_DATABASE\Library\ALTIUM_TOOL\PCB_FOOTPRINTS\Altium_Footprint_Lib.PcbLib; Height: 1.00MM; Library Path: Y:\MIS_DATABASE\Library\ALTIUM_TOOL\SCHEMATICS_PARTS\MS_MISCPOWER_Library.schlib; Mfr_name: TEXAS INSTRUMENTS; Mistral Part No: 142009030403-R; Package: VSON10; Part_type: ICS\POWER\VOLTAGE REGULATOR; Project: BSN-II; RoHS: RoHS; Temperature: -40°C+125°C; Tolerance: NA; Voltage: NA; Wattage: NA; Weight: 26.1mg; Datasheet: Y:\MIS_DATABASE\DATASHEETS\MISC\REGULATORS\TPS748XX.PDF
FID1-FID6 = Fiducial
LBL1 LBL2 = ACCESSORY_THT-3-423-10: ACCESSORIE 1 WORKHORSE POLYSTER LABLE 0.25" X 1"; Chkd/date: MANIRAJA/270218; Crtd /date: ALVY/260218; Footprint Path: Y:\MIS_DATABASE\Library\ALTIUM_TOOL\PCB_FOOTPRINTS\Altium_Footprint_Lib.PcbLib; Library Path: Y:\MIS_DATABASE\Library\ALTIUM_TOOL\SCHEMATICS_PARTS\MS_MECHANICAL_Library.schlib; Mfr_name: BRADY; Mistral Part No: 160018020185; Part_type: ACCESSORIES; Project: TI_MAXIE_CPB
LOGO1 LOGO3-LOGO5 = TI_Logo
LOGO2 LOGO6 = FCC_disclaimer
PCB1 = PCB: AM243x LP EVM Bare PCB REV E3; Mfr_name: ANY

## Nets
0V85_EN: R125.1 R127.2 U21.1(EN)
DGND: C15.2 C18.2 C20.2 C21.2 C22.2 C25.2 C26.2 C27.2 C38.2 C39.2 C48.2 C49.2 C50.2 C51.2 C52.2 C111.2 C122.2 C123.2 C124.2 C125.2 C130.2 C183.2 C218.2 C219.2 C220.2 C222.2 C229.2 LD6.1(CATHODE) Q3.4(S1) Q3.7(S2) R77.2 R90.1 R124.2 R125.2 R232.2 R247.2 TP9.1(TP) TP36.1(TP) TP37.1(TP) TP38.1(TP) U5.5(GND) U5.7(EP) U10.3(AGND) U10.5(PGND) U14.2(GND) U21.3(AGND) U21.5(PGND) U33.6(GND) U33.11(EP) U39.6(GND) U39.11(EP) ; also on sheet 10 11 12 13 14 15 16 17 18 19 20 21 22 23 24 25 26
VDD_1V1: C222.1 C229.1 R248.1 TP30.1(TP) U39.9(OUT1) U39.10(OUT2) ; also on sheet 17 18
VDD_1V1_SS: C183.1 U39.7(SS)
VDD_1V8: R29.2 R30.2 TP5.1(TP) ; also on sheet 10 12 25
VDD_1V8_ENABLE: R31.1 R224.1 U10.8(PG)
VDD_1V8_R: C18.1 C20.1 R30.1 U5.1(OUT)
VDD_2V5: C125.1 C130.1 R81.2 R233.1 TP20.1(TP) U33.9(OUT1) U33.10(OUT2) ; also on sheet 17 18
VDD_2V5_PG: R81.1 U33.3(PG) U39.5(EN)
VDD_2V5_SS: C111.1 U33.7(SS)
VDD_CORE_0V85: C48.1 C49.1 C52.1 C62.1 R96.1 R130.1 TP23.1(TP) ; also on sheet 10 24 25
VDD_CORE_0V85_EN: R29.1 R127.1 U5.3(PG)
VDD_CORE_0V85_FB: C62.2 R124.1 R130.2 U21.2(FB)
VDD_CORE_0V85_PG: Q3.3(G) R112.1 U21.8(PG)
VDD_CORE_0V85_R: C50.1 L2.2 R96.2
VDD_CORE_0V85_SW: L2.1 U21.6(SW)
BOARD_POWER_EN: R84.2 R85.1 U10.1(EN)
FB_1V1: R247.1 R248.2 U39.8(FB)
FB_2V5: R232.1 R233.2 U33.8(FB)
TA_POWERDOWN: R84.1 ; also on sheet 20
VPP_1V8: C38.1 TP51.1(TP) U14.5(OUT) ; also on sheet 24
VPP_1V8_REG_EN: J22.2 R90.2 U14.3(EN)
VPP_1V8_REG_EN_ON: J22.1 R593.1
VSYS_3V3: C15.1 C21.1 C22.1 C27.1 C40.1 C122.1 C124.1 C218.1 C219.1 C220.1 R35.1 R79.1 R80.1 R91.1 R112.2 R224.2 R593.2 TP7.1(TP) U5.6(IN) U33.1(IN1) U33.2(IN2) U33.5(EN) U39.1(IN1) U39.2(IN2) U39.4(BIAS) ; also on sheet 10 11 12 13 14 15 16 17 18 19 20 21 22 23 24 25
VSYS_3V3_FB: C40.2 R77.1 R80.2 U10.2(FB)
VSYS_3V3_R: C26.1 L1.2 R35.2
VSYS_3V3_SW: L1.1 U10.6(SW)
VSYS_5V0: C25.1 C39.1 C51.1 C123.1 R85.2 U10.7(VIN) U14.1(IN) U21.7(VIN) U33.4(BIAS) ; also on sheet 10 13 14 19 20 25 26
N30573184: LD6.2(ANODE) R79.2
N31410611: LD8.2(ANODE) R91.2
N31410626: LD8.1(CATHODE) Q3.1(D1) Q3.2(D2) Q3.5(D3) Q3.6(D4) Q3.8(D5)
N32041451: R31.2 U5.4(EN)

Not connected (* = marked no-connect by the designer): U5 2(NC)*; U10 4(NC)*; U14 4(NC)*; U21 4(NC)*; U39 3(PG)*

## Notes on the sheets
sheet 27
- Core Voltage Generator
- (0.85V, 2A)
- GREEN
- Power Indicator LED
- Isolation Resistor for
  Current Measurement
- To place after Isolation resitor
  on VDD_CORE_0V85 plane
- Peripheral Voltage Generator
- (3.3V, 2A)
- (From test Automation Header
  to Turn OFF the Board)
- Isolation Resistor for
  Current Measurement
- GREEN
- Power Indicator LED
- To place after Isolation resitor
  on VSYS_3V3 plane
sheet 28
- Analog Voltage LDO
- (1.8V, 300mA)
- EPHY LDOs
- eFUSE Programming Voltage LDO
- 3.3V to 2.5V
- (1.8V, 200mA)
- 1.8V @ 200mA
- Insert an external jumper across the
  header J22 to enable the LDO
- 3.3V to 1.1V
sheet 29
- HARDWARE SCHEMATICS
- ASSEMBLY NOTES
- Fiducials
- 1. All MSL components should be baked as per JEDEC standard.
  2. PCB should be baked at 120 degree for 8 hours.
  3. Board assembly must comply with workmanship standards.
  IPC-A-610 Class 2, unless otherwise specified.
  4. These assemblies are ESD sensitive, ESD precautions
  shall be observed.
  5. These assemblies must be clean and free from flux and
  all contaminants. Use of no clean flux is not acceptable.
  6. Provide serial numbers to the assembled boards for identification.
  7. The assembled board are wrapped in ESD Covers(individual) and
  packed securely before shipment.
- BARE PCB
- LABELS
- LOGOs
- Board Serial No.
- Assembly Revision
- Texas Intruments
- TI Launch Pad Logo with web link
- Mistral Solutions
- WEEE Mark
- CE Mark
- For Evaluation only; not FCC approved for resale
